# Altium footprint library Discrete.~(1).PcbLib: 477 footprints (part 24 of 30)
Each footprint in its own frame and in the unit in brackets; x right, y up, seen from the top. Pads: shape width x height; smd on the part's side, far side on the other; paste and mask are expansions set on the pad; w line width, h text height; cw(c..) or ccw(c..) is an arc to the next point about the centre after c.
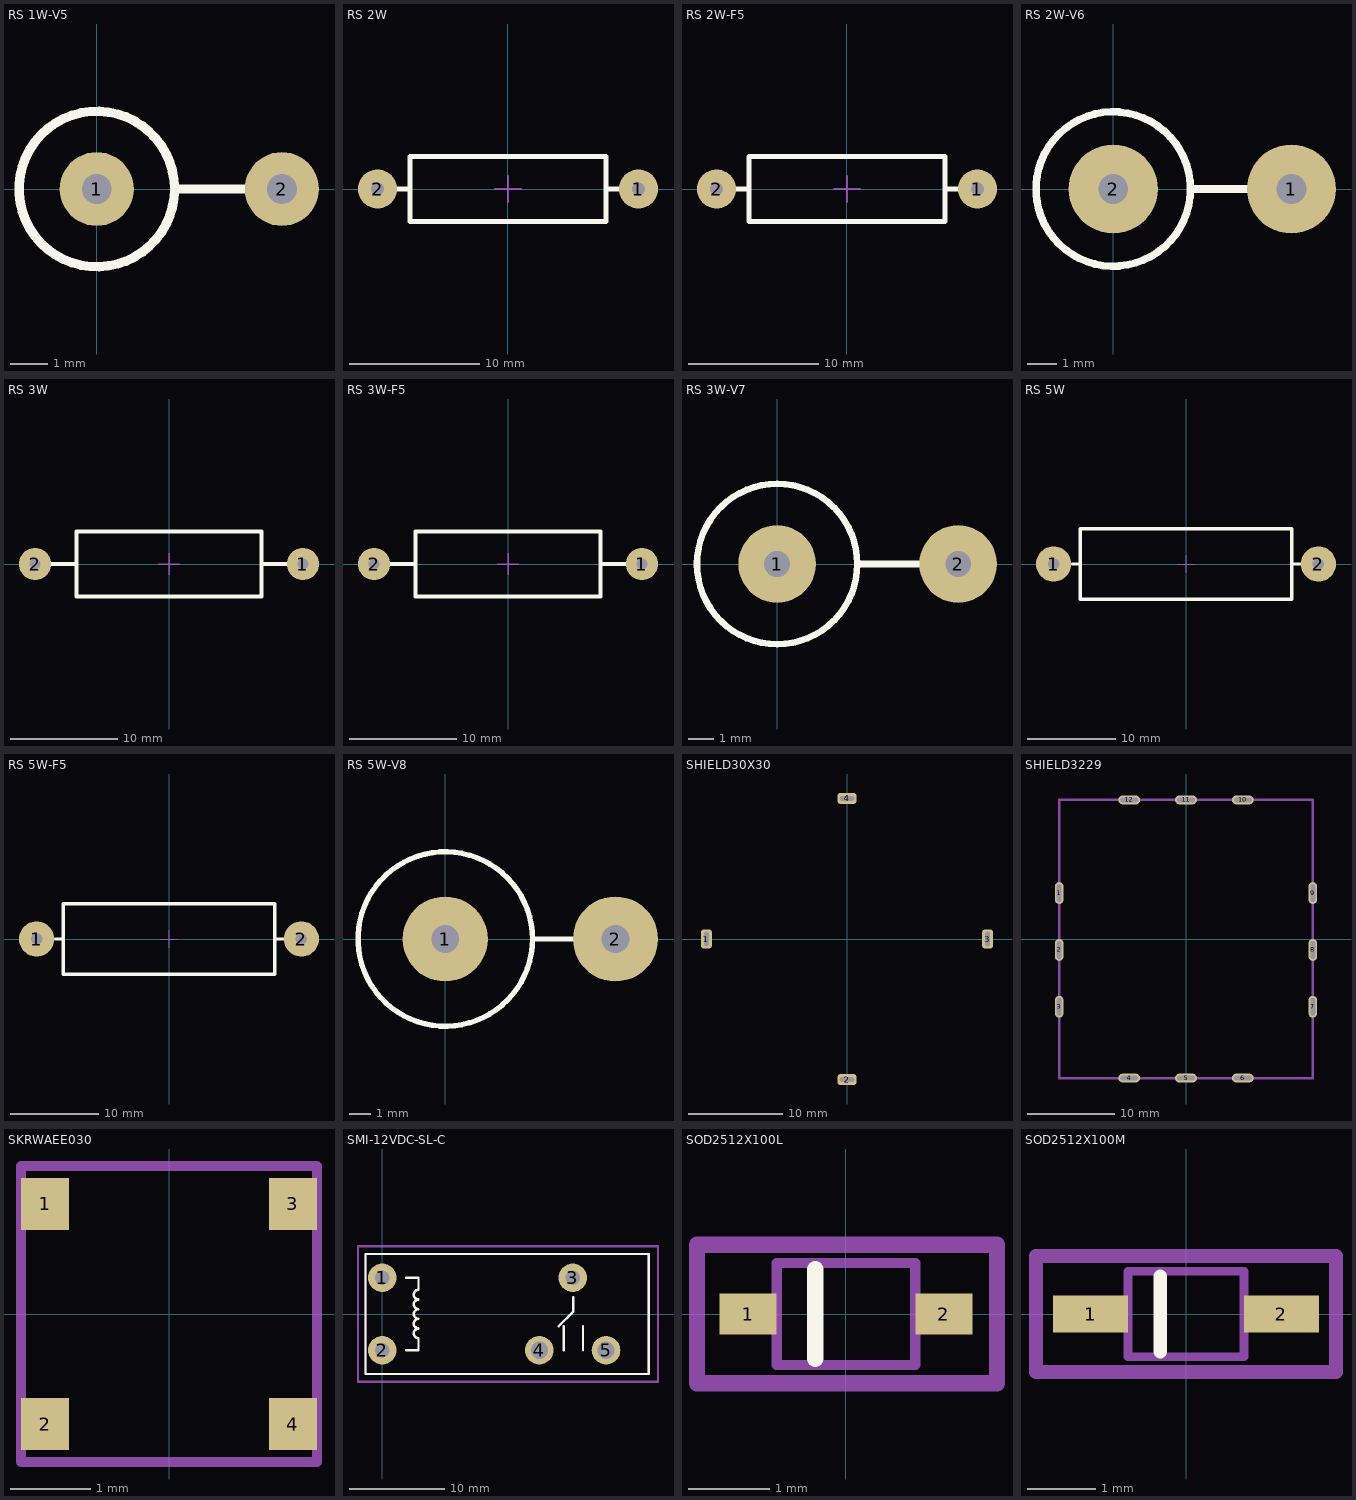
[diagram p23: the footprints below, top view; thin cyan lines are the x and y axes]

## RS 1W-V5 [mm] "直插色环电阻，脚距5mm，直径4mm"
pads (2):
  round 2 hole 0.8: 1(0,0) 2(5,0)
Top Overlay:
  circle w0.254: c0,0 r2.1
  lines w0.254: 2.1,0 4.2,0
3D body "RS 1W-V5.STEP": height 13.3, standoff -3.5, extent -2.01,-2.01 5.3,2.01

## RS 2W [mm] "直插色环电阻，脚距20mm，直径5mm"
pads (2):
  round 3 hole 1: 1(10,0) 2(-10,0)
Top Overlay:
  lines w0.381: -8.5,0 -7.5,0 ; 7.628,0 8.5,0 ; -7.5,-2.5 -7.5,2.5 7.5,2.5 7.5,-2.5 -7.5,-2.5
Mechanical 15:
  lines w0.127: -1.016,0 1.016,0 ; 0,-1.016 0,1.016
3D body "RS 2W.STEP": height 5.11, standoff -3.4, extent -10.4,-2.51 10.4,2.51

## RS 2W-F5 [mm] "直插色环电阻，脚距20mm，直径5mm，浮空5mm"
pads (2):
  round 3 hole 1: 1(10,0) 2(-10,0)
Top Overlay:
  lines w0.381: -8.5,0 -7.5,0 ; 7.628,0 8.5,0 ; -7.5,-2.5 7.5,-2.5 7.5,2.5 -7.5,2.5 -7.5,-2.5
Mechanical 15:
  lines w0.127: -1.016,0 1.016,0 ; 0,-1.016 0,1.016
3D body "RS 2W-F5.STEP": height 10.01, standoff -3.5, extent -10.3,-2.51 10.3,2.51

## RS 2W-V6 [mm] "直插色环电阻，脚距6mm，直径5mm"
pads (2):
  round 3 hole 1: 1(6,0) 2(0,0)
Top Overlay:
  circle w0.254: c0,0 r2.6
  lines w0.254: 2.6,0 5.2,0
3D body "RS 2W-V6.STEP": height 17.6, standoff -3.5, extent -2.51,-2.51 6.4,2.51

## RS 3W [mm] "直插色环电阻，脚距25mm，直径6mm"
pads (2):
  round 3 hole 1: 1(12.5,0) 2(-12.5,0)
Top Overlay:
  lines w0.381: -10.922,0 -8.636,0 ; 8.636,0 11.049,0 ; -8.636,-3.048 8.636,-3.048 8.636,3.048 -8.636,3.048 -8.636,-3.048
Mechanical 15:
  lines w0.127: -1.016,0 1.016,0 ; 0,-1.016 0,1.016
3D body "RS 3W.STEP": height 6.11, standoff -3.4, extent -12.9,-3.01 12.9,3.01

## RS 3W-F5 [mm] "直插色环电阻，脚距25mm，直径6mm，浮空5mm"
pads (2):
  round 3 hole 1: 1(12.5,0) 2(-12.5,0)
Top Overlay:
  lines w0.381: -10.922,0 -8.636,0 ; 8.636,0 11.049,0 ; -8.636,-3.048 8.636,-3.048 8.636,3.048 -8.636,3.048 -8.636,-3.048
Mechanical 15:
  lines w0.127: -1.016,0 1.016,0 ; 0,-1.016 0,1.016
3D body "RS 3W-F5.STEP": height 11.01, standoff -3.5, extent -12.9,-3.01 12.9,3.01

## RS 3W-V7 [mm] "直插色环电阻，脚距7mm，直径6mm"
pads (2):
  round 3 hole 1: 1(0,0) 2(7,0)
Top Overlay:
  circle w0.254: c0,0 r3.1
  lines w0.254: 3.1,0 6.2,0
3D body "RS 3W-V7.STEP": height 19.9, standoff -3.5, extent -3.01,-3.01 7.4,3.01

## RS 5W [mm] "直插色环电阻，脚距30mm，直径8mm"
pads (2):
  round 4 hole 1.3: 1(-15,0) 2(15,0)
Top Overlay:
  lines w0.381: -12.922,0 -12,0 ; 12,0 13,0 ; -12,-4 12,-4 12,4 -12,4 -12,-4
Mechanical 15:
  lines w0.127: -1.016,0 1.016,0 ; 0,-1.016 0,1.016
3D body "RS 5W.STEP": height 8.11, standoff -3.4, extent -15.5,-4.01 15.5,4.01

## RS 5W-F5 [mm] "直插色环电阻，脚距30mm，直径8mm，浮空5mm"
pads (2):
  round 4 hole 1.3: 1(-15,0) 2(15,0)
Top Overlay:
  lines w0.381: -12.922,0 -12,0 ; 12,0 13,0 ; -12,-4 12,-4 12,4 -12,4 -12,-4
Mechanical 15:
  lines w0.127: -1.016,0 1.016,0 ; 0,-1.016 0,1.016
3D body "RS 5W-F5.STEP": height 13.01, standoff -3.5, extent -15.4,-4.01 15.4,4.01

## RS 5W-V8 [mm] "直插色环电阻，脚距8mm，直径8mm"
pads (2):
  round 4 hole 1.3: 1(0,0) 2(8,0)
Top Overlay:
  circle w0.254: c0,0 r4.1
  lines w0.254: 4.1,0 6.25,0
3D body "RS 5W-V8.STEP": height 27.3, standoff -3.5, extent -4.01,-4.01 8.5,4.01

## SHIELD30X30 [mm]
pads (4):
  rrect50% 1.2x2 hole 0.5 slot 1.5 at 90 deg: 1(-15,0) 3(15,0)
  rrect50% 2x1.2 hole 0.5 slot 1.5 at 0 deg: 2(0,-15) 4(0,15)

## SHIELD3229 [mm]
height 6.5
pads (12):
  oval 1x2.5 hole 0.5 slot 2 at 90 deg: 1(-14.5,5.25) 2(-14.5,-1.25) 3(-14.5,-7.75) 7(14.5,-7.75) 8(14.5,-1.25) 9(14.5,5.25)
  oval 2.5x1 hole 0.5 slot 2 at 0 deg: 4(-6.5,-15.9) 5(0,-15.9) 6(6.5,-15.9) 10(6.5,15.9) 11(0,15.9) 12(-6.5,15.9)
Mechanical 13:
  lines w0.3: -14.5,-15.9 14.5,-15.9 14.5,15.9 -14.5,15.9 -14.5,-15.9
3D body: height 6, standoff 0, extent -14.652,15.672 14.554,16.129
3D body: height 6, standoff 0, extent -14.707,-16.154 14.5,-15.697
3D body: height 6, standoff 0, extent 14.094,-16.155 14.5,16.002
3D body: height 6, standoff 0, extent -14.707,-16.154 -14.3,16.002

## SKRWAEE030 [mm]
height 0.35
pads (4):
  rect 0.6x0.65 smd: 1(-1.55,1.375) 2(-1.55,-1.375) 3(1.55,1.375) 4(1.55,-1.375)
Mechanical 13:
  lines w0.127: -1.85,-1.85 -1.85,1.85 1.85,1.85 1.85,-1.85 -1.85,-1.85
3D body: height 0.35, standoff 0, extent -1.85,-1.85 1.85,1.85

## SMI-12VDC-SL-C [mm] "SPDT Relay"
pads (5):
  round 3 hole 1.5: 1(0,3.8) 2(0,-3.8) 3(20,3.8)
  round 3 hole 1.8: 4(16.5,-3.8) 5(23.5,-3.8)
Top Overlay:
  lines w0.254: 2.54,-3.81 3.81,-3.81 3.81,-2.54 ; 2.54,3.81 3.81,3.81 3.81,2.54 ; 3.81,-2.532 cw(c3.81,-2.032) 3.81,-1.532 ; 3.81,-1.516 cw(c3.81,-1.016) 3.81,-0.516 ; 3.81,-0.5 cw(c3.81,0) 3.81,0.5 ; 3.81,0.516 cw(c3.81,1.016) 3.81,1.516 ; 3.81,1.532 cw(c3.81,2.032) 3.81,2.532 ; 18.542,-1.27 20.066,0.254 20.066,1.778 ; 19.05,-3.81 19.05,-1.27 ; 21.082,-3.81 21.082,-1.27 ; 27.94,6.3 28,6.3 ; 28,6.3 -1.75,6.3 -1.75,-6.3 28,-6.3 28,6.3
Mechanical 13:
  lines w0.254: -1.75,-6.3 28,-6.3 28,6.3 -1.75,6.3 -1.75,-6.3
Mechanical 15:
  lines w0.254: -2.54,-7.112 28.956,-7.112 28.956,7.112 -2.54,7.112 -2.54,-7.112
3D body: height 5, standoff -8.5, extent -1.75,-6.3 28,6.3

## SOD2512X100L [mm] "SOD Diode: SOD-323"
height 1
pads (2):
  rect 0.7x0.5 smd: 1(-1.2,0) 2(1.2,0)
Top Overlay:
  lines w0.2: -0.375,-0.55 -0.375,0.55
Mechanical 13:
  lines w0.127: -0.85,-0.625 -0.85,0.625 0.85,0.625 0.85,-0.625 -0.85,-0.625
Mechanical 15:
  lines w0.2: -1.825,-0.85 -1.825,0.85 1.85,0.85 1.85,-0.85 -1.825,-0.85
3D body "SOD-323.STEP": height 1, standoff 0.04, extent -1.311,-0.669 1.337,0.631

## SOD2512X100M [mm] "SOD Diode: SOD-323"
height 1
pads (2):
  rect 1.1x0.55 smd: 1(-1.4,0) 2(1.4,0)
Top Overlay:
  lines w0.2: -0.375,-0.55 -0.375,0.55
Mechanical 13:
  lines w0.127: -0.85,-0.625 0.85,-0.625 0.85,0.625 -0.85,0.625 -0.85,-0.625
Mechanical 15:
  lines w0.2: -2.2,-0.85 2.2,-0.85 2.2,0.85 -2.2,0.85 -2.2,-0.85
3D body "SOD-323.STEP": height 1, standoff 0.04, extent -1.324,-0.65 1.324,0.65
